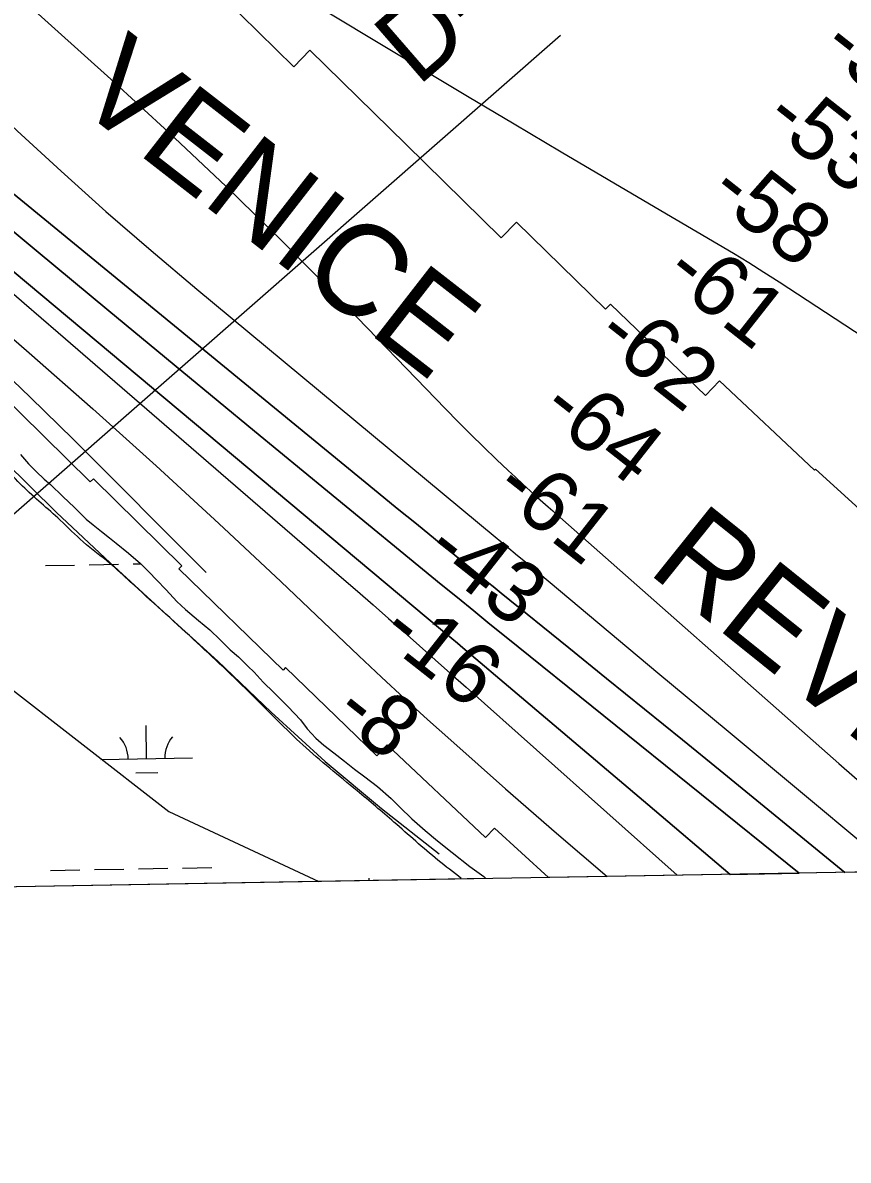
# Model space of a CAD drawing. Extents: x 3892998 to 3931244, y 278583 to 304547.
# Drawn here: x 3914515 to 3915416, y 284015 to 285257 of the extents above; entities that cross this region are included whole.
import ezdxf

# ---------------------------------------------------------------- set-up
doc = ezdxf.new("R2010")
doc.units = 0
for name, color, linetype in [('V-GRID-FRAM', 7, 'Continuous'), ('V-RIVR-EDGE', 7, 'Continuous'), ('V-RIVR-RANG', 7, 'Continuous'), ('V-RIVR-RANG-IDEN', 7, 'Continuous'), ('V-RRAP-FSHR', 7, 'Continuous'), ('V-RRAP-RVMT', 7, 'Continuous'), ('V-RRAP-RVMT-IDEN', 7, 'Continuous'), ('V-SITE-VEGE', 7, 'Continuous'), ('V-TOPO-DPTH', 7, 'Continuous'), ('V-TOPO-MAJR', 7, 'Continuous'), ('V-TOPO-MINR', 7, 'Continuous'), ('V-WETL-SWMP', 7, 'Continuous')]:
    doc.layers.add(name, color=color, linetype=linetype)

msp = doc.modelspace()

# ---------------------------------------------------------------- linework, layer by layer
at = {"layer": 'V-GRID-FRAM'}
msp.add_lwpolyline([(3896958.4, 302195.2), (3928823.6, 302746.7), (3929146.3, 284567.1), (3897265.1, 284015.2), (3896958.4, 302195.2)], dxfattribs=at)
at = {"layer": 'V-RIVR-EDGE'}
msp.add_spline([(3914993.8, 284322.8), (3914968.3, 284342.8), (3914920.3, 284384.2), (3914880.1, 284418.3), (3914821, 284468.4), (3914766.3, 284522), (3914701.3, 284583.8), (3914632.5, 284646.6), (3914610.2, 284666.6), (3914581.2, 284690), (3914556, 284713.8), (3914514.8, 284750.9), (3914475.6, 284794.2), (3914451.8, 284819.5), (3914424.2, 284849.2), (3914397.6, 284877.9), (3914374.8, 284898.3), (3914346.7, 284922.7), (3914310.3, 284952.9), (3914270.1, 284989.9), (3914236.2, 285020.6), (3914181.9, 285072.2), (3914133.5, 285120.4), (3914113.2, 285142.3), (3914088, 285162.3), (3914026.9, 285214.9), (3913985.2, 285250.4), (3913923.7, 285300.6), (3913885.4, 285338.6), (3913828.2, 285387.3), (3913773, 285434), (3913712.4, 285486.1), (3913642.6, 285542.2), (3913620.3, 285557.3), (3913592.7, 285572.4), (3913575.7, 285582.2), (3913557.7, 285592.9), (3913537.8, 285602.2), (3913513.1, 285610), (3913480.6, 285617.8), (3913452, 285625.7), (3913431.6, 285624.8), (3913416.5, 285623.3), (3913398.5, 285612.2), (3913380, 285595.7), (3913368.8, 285578.8), (3913361, 285558.9), (3913353.2, 285538.5), (3913346.8, 285528.8), (3913334.6, 285516.7), (3913321, 285502.7), (3913315.6, 285483.2), (3913310.2, 285462.9), (3913309.7, 285439.5), (3913307.1, 285396.3), (3913306.6, 285384.7), (3913313.4, 285371.6), (3913315.8, 285356.5), (3913316.7, 285340.9), (3913314.3, 285325.4), (3913310.3, 285313.3), (3913303, 285304.1), (3913292.8, 285303.6), (3913281.2, 285304.1), (3913270.5, 285307.6), (3913265.7, 285307.6), (3913263.2, 285304.2), (3913266.1, 285298.3), (3913272.4, 285295.4), (3913294.3, 285287.6), (3913301.5, 285287.6), (3913314.2, 285288), (3913321.9, 285287), (3913325.8, 285283.6), (3913329.7, 285280.7), (3913333.5, 285262.7), (3913334.5, 285242.3), (3913329, 285204.5), (3913324.1, 285171), (3913320.6, 285146.2), (3913319.1, 285121.9), (3913321, 285110.3), (3913321, 285095.7), (3913319.5, 285083.6), (3913315.1, 285061.2), (3913296, 285013.2), (3913271.1, 284963.7), (3913263.3, 284941.4), (3913260.8, 284917.1), (3913261.7, 284891.9), (3913265, 284860.3), (3913263.5, 284819)], degree=3, dxfattribs=at)
at = {"layer": 'V-RIVR-RANG'}
msp.add_line((3914138.9, 284400), (3915102.1, 285243.1), dxfattribs=at)
at = {"layer": 'V-RRAP-FSHR'}
msp.add_lwpolyline([(3913910.3, 285324), (3913970.6, 285271.5), (3914031.8, 285219.8), (3914090.7, 285165.8), (3914149.3, 285111.3), (3914207, 285055.9), (3914264.5, 285000.3), (3914323.2, 284945.9), (3914381.8, 284891.4), (3914438.9, 284835.5), (3914494.9, 284778.3), (3914551.9, 284722.2), (3914610.7, 284667.3), (3914668.9, 284613.7), (3914727.9, 284559.7), (3914786.2, 284504.2), (3914845.3, 284450.4), (3914906.8, 284399.2), (3914969.5, 284349.5)], dxfattribs=at)
at = {"layer": 'V-RRAP-RVMT'}
for p, q in [((3914705.4, 285312.3), (3914811, 285208.6)), ((3914811, 285208.6), (3914828.5, 285226.5)), ((3914828.5, 285226.5), (3914933.1, 285123.9)), ((3914933.1, 285123.9), (3914933.2, 285124)), ((3914933.2, 285124), (3915037.4, 285021.8)), ((3915037.4, 285021.8), (3915053.9, 285038.8)), ((3915053.9, 285038.8), (3915151.2, 284943.9)), ((3915151.2, 284943.9), (3915156.7, 284949.6)), ((3915156.7, 284949.6), (3915260.4, 284849.7)), ((3914588.9, 284755.5), (3914482.5, 284859.9)), ((3915260.4, 284849.7), (3915275.7, 284865.8)), ((3915275.7, 284865.8), (3915379.1, 284768.2)), ((3915379.1, 284768.2), (3915380.3, 284769.4)), ((3915380.3, 284769.4), (3915476.8, 284681.4)), ((3914592.2, 284758.9), (3914588.9, 284755.5)), ((3914688.8, 284664), (3914592.2, 284758.9)), ((3914685.5, 284660.7), (3914688.8, 284664)), ((3914799.3, 284549.9), (3914685.5, 284660.7)), ((3914802, 284552.8), (3914799.3, 284549.9)), ((3914901.6, 284456.7), (3914802, 284552.8)), ((3914913, 284468.5), (3914901.6, 284456.7)), ((3915020.3, 284367.4), (3914913, 284468.5)), ((3915029.9, 284377.6), (3915020.3, 284367.4)), ((3915088.9, 284323.8), (3915029.9, 284377.6)), ((3915957.6, 284338.8), (3915088.9, 284323.8))]:
    msp.add_line(p, q, dxfattribs=at)
at = {"layer": 'V-SITE-VEGE'}
for p, q in [((3914463.8, 284559.8), (3914674.5, 284395.9)), ((3914674.5, 284395.9), (3914838.2, 284319.4)), ((3914838.2, 284319.4), (3913226.8, 284291.5))]:
    msp.add_line(p, q, dxfattribs=at)
at = {"layer": 'V-TOPO-DPTH'}
msp.add_line((3915287.3, 284327.2), (3915362.5, 284328.5), dxfattribs=at)
for points in [[(3915362.5, 284328.5), (3915042.9, 284585.9), (3915025, 284600.3), (3915007.3, 284614.7), (3914989.5, 284629.2), (3914971.8, 284643.7), (3914847.8, 284745.4), (3914768.2, 284810.9), (3914688.7, 284876.4), (3914609.2, 284942.1), (3914529.9, 285007.9), (3914388.8, 285125.2), (3914370.2, 285140.7), (3914351.6, 285156.4), (3914333.3, 285172.3), (3914315, 285188.3), (3914118.6, 285361.1), (3914060.1, 285412.9), (3914001.9, 285464.9), (3913944, 285517.3), (3913886.3, 285570)], [(3915362.5, 284328.5), (3915042.9, 284585.9), (3915025, 284600.3), (3915007.3, 284614.7), (3914989.5, 284629.2), (3914971.8, 284643.7), (3914847.8, 284745.4), (3914768.2, 284810.9), (3914688.7, 284876.4), (3914609.2, 284942.1), (3914529.9, 285007.9), (3914388.8, 285125.2), (3914370.2, 285140.7), (3914351.6, 285156.4), (3914333.3, 285172.3), (3914315, 285188.3), (3914118.6, 285361.1), (3914060.1, 285412.9), (3914018.1, 285450.4)], [(3914018.1, 285450.4), (3914093.5, 285327.6), (3914122.5, 285304.2), (3914315.7, 285143.3), (3914322.9, 285137.3), (3914330, 285131.3), (3914337.2, 285125.3), (3914344.4, 285119.3), (3914388.5, 285082.3), (3914417.8, 285057.7), (3914447.1, 285033.2), (3914476.3, 285008.7), (3914505.6, 284984.2), (3914971.2, 284594.7), (3914977.3, 284589.6), (3914983.4, 284584.5), (3914989.5, 284579.4), (3914995.6, 284574.3), (3915054.8, 284524.2), (3915090.5, 284494), (3915126.2, 284463.8), (3915161.8, 284433.6), (3915197.5, 284403.4), (3915287.3, 284327.2)], [(3915287.3, 284327.2), (3915197.5, 284403.4), (3915161.8, 284433.6), (3915126.2, 284463.8), (3915090.5, 284494), (3915054.8, 284524.2), (3914995.6, 284574.3), (3914989.5, 284579.4), (3914983.4, 284584.5), (3914977.3, 284589.6), (3914971.2, 284594.7), (3914505.6, 284984.2), (3914476.3, 285008.7), (3914447.1, 285033.2), (3914417.8, 285057.7), (3914388.5, 285082.3), (3914344.4, 285119.3), (3914337.2, 285125.3), (3914330, 285131.3), (3914322.9, 285137.3), (3914315.7, 285143.3), (3914122.5, 285304.2), (3914093.5, 285327.6)], [(3914275.6, 285264.8), (3914307.1, 285235.9), (3914357.6, 285191.2), (3914364.4, 285185.2), (3914371.3, 285179.3), (3914378.3, 285173.4), (3914385.3, 285167.6), (3914903.1, 284743.7), (3914923.9, 284726.6), (3914944.8, 284709.6), (3914965.7, 284692.5), (3914986.6, 284675.5), (3915019.4, 284648.7), (3915023.9, 284645.1), (3915028.4, 284641.4), (3915032.9, 284637.8), (3915037.4, 284634.1), (3915111.1, 284574.5), (3915152.4, 284541), (3915193.7, 284507.5), (3915235, 284473.9), (3915276.2, 284440.4), (3915412.3, 284329.4)], [(3917760.4, 284370), (3915412.3, 284329.4), (3915276.2, 284440.4), (3915235, 284473.9), (3915193.7, 284507.5), (3915152.4, 284541), (3915111.1, 284574.5), (3915037.4, 284634.1), (3915032.9, 284637.8), (3915028.4, 284641.4), (3915023.9, 284645.1), (3915019.4, 284648.7), (3914986.6, 284675.5), (3914965.7, 284692.5), (3914944.8, 284709.6), (3914923.9, 284726.6), (3914903.1, 284743.7), (3914385.3, 285167.6), (3914378.3, 285173.4), (3914371.3, 285179.3), (3914364.4, 285185.2), (3914357.6, 285191.2), (3914307.1, 285235.9), (3914275.6, 285264.8)], [(3914138, 285198.6), (3914147.7, 285193.3), (3914240.8, 285130.2), (3914268.3, 285110.9), (3914295.4, 285090.8), (3914321.7, 285069.9), (3914347.5, 285048.2), (3914522.2, 284896.4), (3914591.8, 284835.1), (3914660.9, 284773.1), (3914729.2, 284710.2), (3914796.8, 284646.7), (3914882, 284565.6), (3914906.8, 284542.3), (3914931.8, 284519.1), (3914957, 284496.2), (3914982.3, 284473.5), (3915042.1, 284420.6), (3915097.8, 284372), (3915152.9, 284324.9)]]:
    msp.add_lwpolyline(points, dxfattribs=at)
at = {"layer": 'V-TOPO-MAJR'}
msp.add_lwpolyline([(3914376.7, 285267.3), (3914395.2, 285247.9), (3914413.9, 285228.7), (3914433.1, 285210), (3914452.5, 285191.4), (3914508.9, 285138.7), (3914557, 285094.4), (3914605.7, 285050.7), (3914655.2, 285007.9), (3914705.2, 284965.7), (3915030.9, 284695.6), (3915043, 284685.4), (3915055.2, 284675.3), (3915067.4, 284665.2), (3915079.5, 284655.1), (3915208.4, 284547.3), (3915285.1, 284483.3), (3915361.8, 284419.4), (3915438.5, 284355.5)], dxfattribs=at)
at = {"layer": 'V-TOPO-MINR'}
for points in [[(3913886.3, 285570), (3913944, 285517.3), (3914001.9, 285464.9), (3914060.1, 285412.9), (3914118.6, 285361.1), (3914315, 285188.3), (3914333.3, 285172.3), (3914351.6, 285156.4), (3914370.2, 285140.7), (3914388.8, 285125.2), (3914529.9, 285007.9), (3914609.2, 284942.1), (3914688.7, 284876.4), (3914768.2, 284810.9), (3914847.8, 284745.4), (3914971.8, 284643.7), (3914989.5, 284629.2), (3915007.3, 284614.7), (3915025, 284600.3), (3915042.9, 284585.9), (3915362.5, 284328.5)], [(3915473.5, 284886.4), (3915340.5, 284973.5), (3915324.1, 284984.1), (3915307.6, 284994.5), (3915291, 285004.6), (3915274.2, 285014.6), (3915205.2, 285054.9), (3915153.9, 285085), (3915102.7, 285115.2), (3915051.6, 285145.7), (3915000.6, 285176.2), (3914591.4, 285422.4)], [(3914093.5, 285327.6), (3914122.5, 285304.2), (3914315.7, 285143.3), (3914322.9, 285137.3), (3914330, 285131.3), (3914337.2, 285125.3), (3914344.4, 285119.3), (3914388.5, 285082.3), (3914417.8, 285057.7), (3914447.1, 285033.2), (3914476.3, 285008.7), (3914505.6, 284984.2), (3914971.2, 284594.7), (3914977.3, 284589.6), (3914983.4, 284584.5), (3914989.5, 284579.4), (3914995.6, 284574.3), (3915054.8, 284524.2), (3915090.5, 284494), (3915126.2, 284463.8), (3915161.8, 284433.6), (3915197.5, 284403.4), (3915287.3, 284327.2)], [(3914517.7, 285279.1), (3914611.4, 285194.9), (3914674.7, 285136.8), (3914737.2, 285077.9), (3914798.5, 285017.7), (3914858.9, 284956.6), (3914976.5, 284835.2), (3914990.2, 284821.2), (3915004, 284807.3), (3915018.1, 284793.6), (3915032.2, 284780), (3915044.8, 284768.1), (3915052.8, 284760.6), (3915060.8, 284753.1), (3915068.9, 284745.7), (3915077.1, 284738.4), (3915088.6, 284728.2), (3915091.1, 284726), (3915093.5, 284723.8), (3915096, 284721.7), (3915098.5, 284719.5), (3915405.8, 284448.2), (3915460, 284400.8)], [(3914275.6, 285264.8), (3914307.1, 285235.9), (3914357.6, 285191.2), (3914364.4, 285185.2), (3914371.3, 285179.3), (3914378.3, 285173.4), (3914385.3, 285167.6), (3914903.1, 284743.7), (3914923.9, 284726.6), (3914944.8, 284709.6), (3914965.7, 284692.5), (3914986.6, 284675.5), (3915019.4, 284648.7), (3915023.9, 284645.1), (3915028.4, 284641.4), (3915032.9, 284637.8), (3915037.4, 284634.1), (3915111.1, 284574.5), (3915152.4, 284541), (3915193.7, 284507.5), (3915235, 284473.9), (3915276.2, 284440.4), (3915412.3, 284329.4)], [(3914138, 285198.6), (3914147.7, 285193.3), (3914240.8, 285130.2), (3914268.3, 285110.9), (3914295.4, 285090.8), (3914321.7, 285069.9), (3914347.5, 285048.2), (3914522.2, 284896.4), (3914591.8, 284835.1), (3914660.9, 284773.1), (3914729.2, 284710.2), (3914796.8, 284646.7), (3914882, 284565.6), (3914906.8, 284542.3), (3914931.8, 284519.1), (3914957, 284496.2), (3914982.3, 284473.5), (3915042.1, 284420.6), (3915097.8, 284372), (3915152.9, 284324.9)], [(3914171, 285138.5), (3914178.1, 285135.6), (3914193.3, 285127.3), (3914245.9, 285091.6), (3914261.5, 285080.7), (3914276.8, 285069.3), (3914291.6, 285057.4), (3914306.2, 285045.1), (3914377.2, 284982.8), (3914426.6, 284938.6), (3914475.4, 284893.8), (3914523.3, 284848), (3914570.6, 284801.6), (3914715.4, 284656.7)], [(3914479.8, 284982.3), (3914516.8, 284950.5), (3914553.7, 284918.7), (3914863.2, 284651.2), (3914880.3, 284636.4), (3914897.4, 284621.5), (3914914.4, 284606.5), (3914931.3, 284591.6), (3914948.3, 284576.5), (3914965.2, 284561.5), (3914982.1, 284546.4), (3914999, 284531.4), (3915229.5, 284326.2)]]:
    msp.add_lwpolyline(points, dxfattribs=at)
at = {"layer": 'V-WETL-SWMP'}
for p, q in [((3914512.6, 284785.3), (3914521.4, 284775.3)), ((3914521.4, 284775.3), (3914529.8, 284766.9)), ((3914529.8, 284766.9), (3914538.4, 284758.5)), ((3914538.4, 284758.5), (3914545.4, 284752.5)), ((3914545.4, 284752.5), (3914559, 284739.6)), ((3914559, 284739.6), (3914571.6, 284727.6)), ((3914571.6, 284727.6), (3914584.2, 284715)), ((3914584.2, 284715), (3914592, 284708.6)), ((3914592, 284708.6), (3914601.2, 284701.4)), ((3914601.2, 284701.4), (3914610, 284694.6)), ((3914610, 284694.6), (3914617, 284688.8)), ((3914617, 284688.8), (3914630.4, 284677.8)), ((3914630.4, 284677.8), (3914643.6, 284666.6)), ((3914539.8, 284664.2), (3914571.8, 284664.8)), ((3914587.8, 284665), (3914619.8, 284665.6)), ((3914635.8, 284665.9), (3914644.2, 284666)), ((3914643.6, 284666.6), (3914653, 284657)), ((3914653, 284657), (3914661.2, 284648.6)), ((3914661.2, 284648.6), (3914671.8, 284637.6)), ((3914671.8, 284637.6), (3914683.2, 284625)), ((3914683.2, 284625), (3914692.8, 284616.2)), ((3914692.8, 284616.2), (3914707.1, 284604.2)), ((3914707.1, 284604.2), (3914719.3, 284594.2)), ((3914719.3, 284594.2), (3914730.7, 284583.2)), ((3914730.7, 284583.2), (3914741.5, 284572.2)), ((3914741.5, 284572.2), (3914750.5, 284564.6)), ((3914750.5, 284564.6), (3914760.7, 284554.4)), ((3914760.7, 284554.4), (3914767.7, 284547.8)), ((3914767.7, 284547.8), (3914777.5, 284536.8)), ((3914777.5, 284536.8), (3914789.3, 284525.5)), ((3914789.3, 284525.5), (3914804.9, 284509.9)), ((3914804.9, 284509.9), (3914818.1, 284495.7)), ((3914818.1, 284495.7), (3914825.5, 284486.1)), ((3914650.3, 284453.5), (3914649.7, 284489.5)), ((3914825.5, 284486.1), (3914834.9, 284475.9)), ((3914834.9, 284475.9), (3914843.9, 284468.3)), ((3914843.9, 284468.3), (3914854.5, 284459.9)), ((3914854.5, 284459.9), (3914866.3, 284450.7)), ((3914600.3, 284452.6), (3914700.3, 284454.4)), ((3914866.3, 284450.7), (3914877.3, 284441.9)), ((3914638.6, 284437.9), (3914662.5, 284438.3)), ((3914877.3, 284441.9), (3914888.5, 284433.5)), ((3914888.5, 284433.5), (3914902.3, 284423.1)), ((3914902.3, 284423.1), (3914917.1, 284410.1)), ((3914917.1, 284410.1), (3914926.7, 284400.5)), ((3914926.7, 284400.5), (3914939.8, 284387.9)), ((3914939.8, 284387.9), (3914954.4, 284374.9)), ((3914954.4, 284374.9), (3914967.8, 284363.7)), ((3914967.8, 284363.7), (3914983.8, 284351.1)), ((3914983.8, 284351.1), (3915003.2, 284335.9)), ((3914641.5, 284333.2), (3914673.5, 284333.8)), ((3914689.5, 284334.1), (3914721.5, 284334.6)), ((3915003.2, 284335.9), (3915018.2, 284325)), ((3915020.6, 284322.6), (3913193.8, 284291)), ((3914545.5, 284331.6), (3914577.5, 284332.1)), ((3914593.5, 284332.4), (3914625.5, 284333)), ((3914893.1, 284320.4), (3914893.1, 284322.9)), ((3915018.2, 284325), (3915020.6, 284322.6))]:
    msp.add_line(p, q, dxfattribs=at)
for centre, start, end in [((3914595, 284453), 0.2199, 41.7635), ((3914705.5, 284454.9), 140.2199, 181.7635)]:
    msp.add_arc(centre, 35.2, start, end, dxfattribs=at)

# ---------------------------------------------------------------- texts
at = {"layer": 'V-RIVR-RANG'}
for s, rotation, p in [('-52', 321.8105, (3915383.7, 285224.7)), ('-53', 321.8105, (3915321.3, 285146.6)), ('-58', 321.8105, (3915261.3, 285066.5)), ('-61', 321.8105, (3915212.4, 284977.8)), ('-62', 321.8105, (3915137.3, 284909.6)), ('-64', 321.8105, (3915077.6, 284829.4)), ('-61', 321.8105, (3915026.3, 284742.4)), ('-43', 321.8105, (3914950.8, 284674.6)), ('-16', 321.8105, (3914902.1, 284585.7)), ('-8', 321.5283, (3914851.7, 284498.4))]:
    msp.add_text(s, height=67, rotation=rotation, dxfattribs=at).set_placement(p)
at = {"layer": 'V-RIVR-RANG-IDEN'}
msp.add_text('D-240', height=83, rotation=40.9357, dxfattribs=at).set_placement((3914946.3, 285186.2))
at = {"layer": 'V-RRAP-RVMT-IDEN'}
for s, rotation, p in [('VENICE', 322.116, (3914568.1, 285170.2)), ('REVET.', 321.2756, (3915195.3, 284657.7))]:
    msp.add_text(s, height=100, rotation=rotation, dxfattribs=at).set_placement(p)

doc.saveas('drawing.dxf')
